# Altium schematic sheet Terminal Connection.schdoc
size 244 x 207 mm
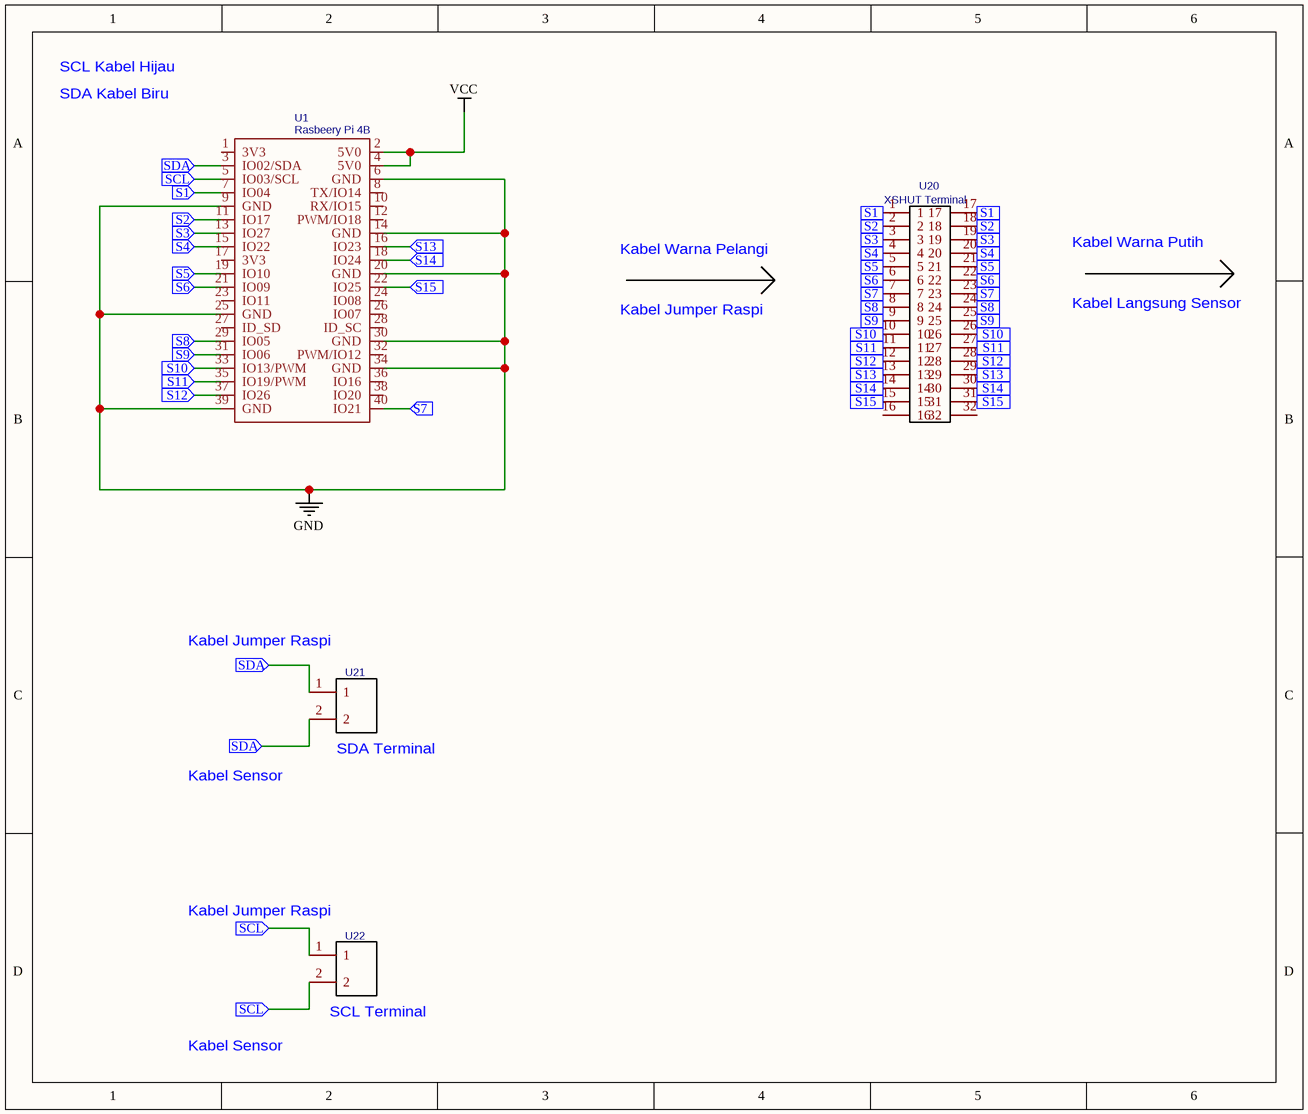
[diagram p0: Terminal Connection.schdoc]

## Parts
U1  Rasbeery Pi 4B
U20  XSHUT Terminal
U21  NO  (value not drawn)
U22  NO  (value not drawn)

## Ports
S1 (in), S2 (in), S3 (in), S4 (in), S5 (in), S6 (in), S7 (in), S8 (in), S9 (in), S10 (in), S11 (in), S12 (in), S13 (in), S14 (in), S15 (in), SCL (in), SDA (in)

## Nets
GND: U1.6(GND) U1.9(GND) U1.14(GND) U1.20(GND) U1.25(GND) U1.30(GND) U1.34(GND) U1.39(GND)
VCC: U1.2(5V0) U1.4(5V0)
S1: U1.7(IO04) U20.1 U20.17 ; port S1
S2: U1.11(IO17) U20.2 U20.18 ; port S2
S3: U1.13(IO27) U20.3 U20.19 ; port S3
S4: U1.15(IO22) U20.4 U20.20 ; port S4
S5: U1.19(IO10) U20.5 U20.21 ; port S5
S6: U1.21(IO09) U20.6 U20.22 ; port S6
S7: U1.40(IO21) U20.7 U20.23 ; port S7
S8: U1.29(IO05) U20.8 U20.24 ; port S8
S9: U1.31(IO06) U20.9 U20.25 ; port S9
S10: U1.33(IO13/PWM) U20.10 U20.26 ; port S10
S11: U1.35(IO19/PWM) U20.11 U20.27 ; port S11
S12: U1.37(IO26) U20.12 U20.28 ; port S12
S13: U1.16(IO23) U20.13 U20.29 ; port S13
S14: U1.18(IO24) U20.14 U20.30 ; port S14
S15: U1.22(IO25) U20.15 U20.31 ; port S15
SCL: U1.5(IO03/SCL) U22.1 U22.2 ; port SCL
SDA: U1.3(IO02/SDA) U21.1 U21.2 ; port SDA

Not connected (* = marked no-connect by the designer): U1 1(3V3) 8(TX/IO14) 10(RX/IO15) 12(PWM/IO18) 17(3V3) 23(IO11) 24(IO08) 26(IO07) 27(ID_SD) 28(ID_SC) 32(PWM/IO12) 36(IO16) 38(IO20); U20 16 32

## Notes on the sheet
- SCL Kabel Hijau
- SDA Kabel Biru
- Kabel Warna Pelangi
- Kabel Warna Putih
- Kabel Jumper Raspi
- Kabel Langsung Sensor
- (near U21) Kabel Jumper Raspi
- Kabel Sensor
- (near U21) SDA Terminal
- (near U22) Kabel Jumper Raspi
- (near U22) SCL Terminal

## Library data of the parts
U1 = Rasbeery Pi 4B: Contributor: vinconloren
U20 = XSHUT Terminal: Contributor: Vinsensius Reinard
U21 U22 = NO: Contributor: Vinsensius Reinard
